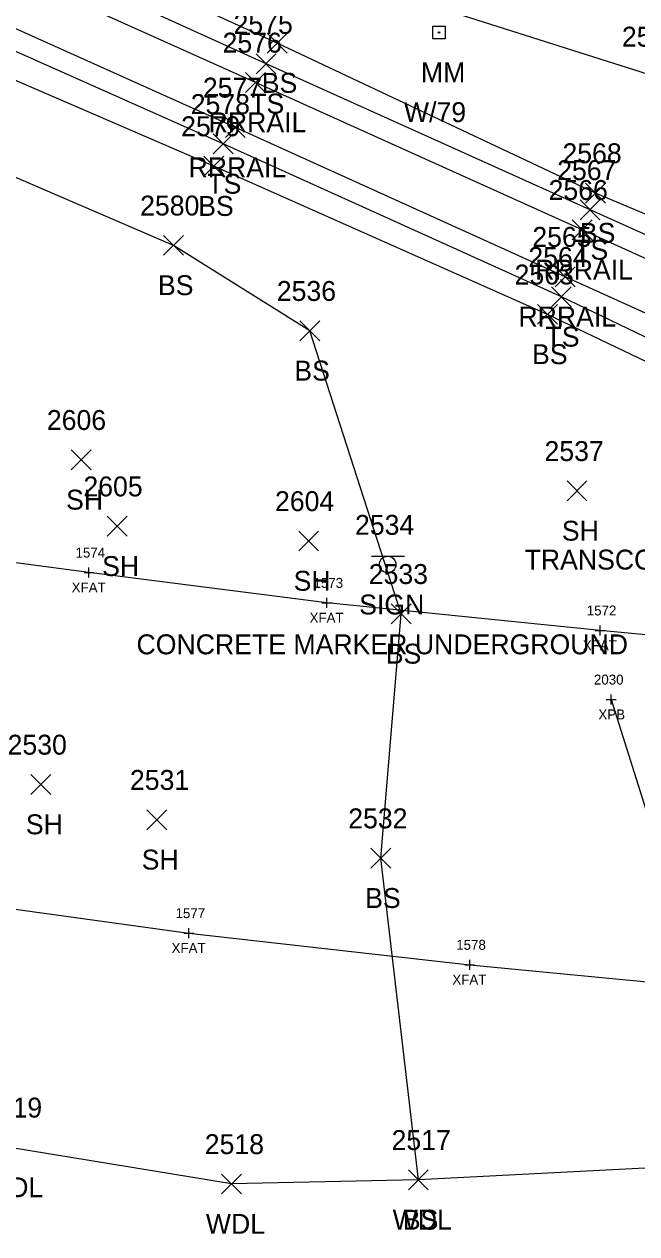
# Model space of a CAD drawing. Extents: x 1599569 to 1610055, y 642560 to 647860.
# Drawn here: x 1601133.3 to 1601194.8, y 647218.8 to 647340.3 of the extents above; entities that cross this region are included whole.
import ezdxf

# ---------------------------------------------------------------- set-up
doc = ezdxf.new("R2010")
doc.units = 0
for name, color, linetype in [('B_A', 7, 'Continuous'), ('B_I', 7, 'Continuous'), ('B_TIC', 7, 'Continuous'), ('BF', 7, 'Continuous'), ('BSUBM', 7, 'Continuous'), ('L_A', 7, 'Continuous'), ('L_I', 7, 'Continuous'), ('L_TIC', 7, 'Continuous'), ('LAWA', 7, 'Continuous'), ('LELB', 7, 'Continuous'), ('R_A', 7, 'Continuous'), ('R_I', 7, 'Continuous'), ('R_TIC', 7, 'Continuous'), ('RR', 7, 'Continuous'), ('S_A', 7, 'Continuous'), ('S_C', 7, 'Continuous'), ('S_I', 7, 'Continuous'), ('SRM', 7, 'Continuous'), ('SSGN', 7, 'Continuous')]:
    doc.layers.add(name, color=color, linetype=linetype)

msp = doc.modelspace()

# ---------------------------------------------------------------- linework, layer by layer
at = {"layer": 'B_TIC'}
for p, q in [((1601139.85, 647285.25), (1601139.93, 647285.25)), ((1601163.73, 647282.21), (1601163.81, 647282.21)), ((1601191.16, 647279.44), (1601191.24, 647279.44)), ((1601192.25, 647272.5), (1601192.33, 647272.5)), ((1601149.89, 647249.04), (1601149.96, 647249.04)), ((1601178.06, 647245.86), (1601178.14, 647245.86))]:
    msp.add_line(p, q, dxfattribs=at)
for points in [[(1601139.85, 647284.75), (1601139.85, 647285.75)], [(1601139.35, 647285.25), (1601140.35, 647285.25)], [(1601163.23, 647282.21), (1601164.23, 647282.21)], [(1601163.73, 647281.71), (1601163.73, 647282.71)], [(1601191.16, 647278.94), (1601191.16, 647279.94)], [(1601190.66, 647279.44), (1601191.66, 647279.44)], [(1601191.75, 647272.5), (1601192.75, 647272.5)], [(1601192.25, 647272), (1601192.25, 647273)], [(1601149.88, 647248.54), (1601149.88, 647249.54)], [(1601149.38, 647249.04), (1601150.38, 647249.04)], [(1601177.56, 647245.86), (1601178.56, 647245.86)], [(1601178.06, 647245.36), (1601178.06, 647246.36)]]:
    msp.add_lwpolyline(points, dxfattribs=at)
at = {"layer": 'BF'}
for points in [[(1601321.94, 647272.73), (1601290.34, 647273.17), (1601259.98, 647274.32), (1601229.43, 647276.17), (1601206.22, 647277.99), (1601191.16, 647279.44), (1601163.73, 647282.21), (1601139.85, 647285.25), (1601124.64, 647287.26)], [(1601119.61, 647253.21), (1601149.88, 647249.04), (1601178.06, 647245.86), (1601200.07, 647243.74), (1601226.76, 647241.55), (1601258.61, 647239.74), (1601288.62, 647238.61), (1601320.66, 647238.01)]]:
    msp.add_lwpolyline(points, dxfattribs=at)
at = {"layer": 'BSUBM'}
msp.add_lwpolyline([(1601192.25, 647272.5), (1601199.21, 647250.42)], dxfattribs=at)
at = {"layer": 'L_TIC'}
for points in [[(1601157.75, 647337.43), (1601159.75, 647339.43)], [(1601159.75, 647337.43), (1601157.75, 647339.43)], [(1601156.62, 647335.35), (1601158.62, 647337.35)], [(1601158.62, 647335.35), (1601156.62, 647337.35)], [(1601152.32, 647327.3), (1601154.32, 647329.3)], [(1601154.32, 647327.3), (1601152.32, 647329.3)], [(1601151.37, 647325.07), (1601153.37, 647327.07)], [(1601153.37, 647325.07), (1601151.37, 647327.07)], [(1601189.68, 647322.36), (1601191.68, 647324.36)], [(1601191.68, 647322.36), (1601189.68, 647324.36)], [(1601189.14, 647320.67), (1601191.14, 647322.67)], [(1601191.14, 647320.67), (1601189.14, 647322.67)], [(1601147.33, 647317.11), (1601149.33, 647319.11)], [(1601149.33, 647317.11), (1601147.33, 647319.11)], [(1601186.26, 647311.94), (1601188.26, 647313.94)], [(1601188.26, 647311.94), (1601186.26, 647313.94)], [(1601184.88, 647310.18), (1601186.88, 647312.18)], [(1601186.88, 647310.18), (1601184.88, 647312.18)], [(1601161.02, 647308.53), (1601163.02, 647310.53)], [(1601163.02, 647308.53), (1601161.02, 647310.53)], [(1601138.06, 647295.57), (1601140.06, 647297.57)], [(1601140.06, 647295.57), (1601138.06, 647297.57)], [(1601187.83, 647292.45), (1601189.83, 647294.45)], [(1601189.83, 647292.45), (1601187.83, 647294.45)], [(1601141.68, 647288.9), (1601143.68, 647290.9)], [(1601143.68, 647288.9), (1601141.68, 647290.9)], [(1601160.9, 647287.42), (1601162.9, 647289.42)], [(1601162.9, 647287.42), (1601160.9, 647289.42)], [(1601170.19, 647280.1), (1601172.19, 647282.1)], [(1601172.19, 647280.1), (1601170.19, 647282.1)], [(1601134.03, 647262.96), (1601136.03, 647264.96)], [(1601136.03, 647262.96), (1601134.03, 647264.96)], [(1601145.65, 647259.42), (1601147.65, 647261.42)], [(1601147.65, 647259.42), (1601145.65, 647261.42)], [(1601168.13, 647255.56), (1601170.13, 647257.56)], [(1601170.13, 647255.56), (1601168.13, 647257.56)], [(1601171.91, 647223.25), (1601173.91, 647225.25)], [(1601173.91, 647223.25), (1601171.91, 647225.25)], [(1601171.91, 647223.25), (1601173.91, 647225.25)], [(1601173.91, 647223.25), (1601171.91, 647225.25)], [(1601153.16, 647222.84), (1601155.16, 647224.84)], [(1601155.16, 647222.84), (1601153.16, 647224.84)]]:
    msp.add_lwpolyline(points, dxfattribs=at)
at = {"layer": 'LAWA'}
msp.add_lwpolyline([(1601306.6, 647220.69), (1601276.84, 647227.54), (1601234.69, 647231.8), (1601218.85, 647229.04), (1601213.51, 647228.99), (1601209.45, 647227.68), (1601199.57, 647225.62), (1601172.91, 647224.25), (1601154.16, 647223.84), (1601131.9, 647227.51), (1601118.99, 647241.56), (1601106.98, 647246.07), (1601045.88, 647251.39), (1601009.79, 647259.81), (1600973.15, 647266.08), (1600946.11, 647265.67), (1600904.1, 647280.51), (1600862.74, 647296.26), (1600826.18, 647313.68), (1600771.19, 647334.59)], dxfattribs=at)
at = {"layer": 'LELB'}
for points in [[(1601329.86, 647260.18), (1601292.61, 647278.06), (1601262.72, 647292.4), (1601226.59, 647308.21), (1601190.68, 647323.36), (1601158.75, 647338.43), (1601129.91, 647351.62), (1601096.68, 647366.43), (1601056.58, 647384.54), (1601012.74, 647404.18), (1600965.22, 647426.07), (1600914.49, 647448.77), (1600866.79, 647471.13), (1600821.34, 647492.23), (1600763.72, 647518.52)], [(1601329.08, 647258.95), (1601292.39, 647275.61), (1601261.46, 647289.71), (1601225.27, 647305.87), (1601190.14, 647321.67), (1601157.62, 647336.35), (1601128.98, 647349.36), (1601095.53, 647364.39), (1601055.96, 647382.57), (1601011.7, 647402.22), (1600964.35, 647423.93), (1600913.28, 647446.74), (1600865.78, 647468.67), (1600819.14, 647488.99), (1600762.95, 647515.26)], [(1601326.17, 647250.65), (1601291.06, 647266.1), (1601257.88, 647281.25), (1601220.45, 647296.99), (1601187.26, 647312.94), (1601153.32, 647328.3), (1601124.87, 647340.95), (1601091.41, 647355.79), (1601053.43, 647373.03), (1601007.18, 647393.84), (1600960.43, 647415.03), (1600909.23, 647438.57), (1600861.95, 647459.92), (1600814.78, 647480.92), (1600758.97, 647506.06)], [(1601324.87, 647247.72), (1601290.33, 647262.4), (1601257.07, 647278.05), (1601219.4, 647295.14), (1601185.88, 647311.18), (1601152.37, 647326.07), (1601123.71, 647338.45), (1601090.36, 647353.63), (1601052.5, 647371.13), (1601006, 647391.96), (1600959.19, 647412.11), (1600907.65, 647435.58), (1600860.78, 647455.97), (1600813.3, 647477.78), (1600757.71, 647501.96)], [(1601277.64, 647306.94), (1601247.91, 647313.96), (1601233.47, 647321.04), (1601196.65, 647335.07), (1601162.36, 647345.97), (1601131.17, 647354.49), (1601097.9, 647368.75), (1601057.17, 647386.63), (1601013.7, 647406.22), (1600966.1, 647427.78), (1600916.08, 647451.44), (1600867.43, 647472.68), (1600824.54, 647496.94)], [(1601172.91, 647224.25), (1601169.13, 647256.56), (1601171.19, 647281.1), (1601162.02, 647309.53), (1601148.33, 647318.11), (1601119.88, 647330.36), (1601083.79, 647337.85), (1601042.57, 647341.43), (1601006.37, 647351.71), (1600962.47, 647358.64), (1600928.59, 647369.58)]]:
    msp.add_lwpolyline(points, dxfattribs=at)
at = {"layer": 'R_TIC'}
for points in [[(1601155.57, 647333.47), (1601157.57, 647335.47)], [(1601157.57, 647333.47), (1601155.57, 647335.47)], [(1601153.54, 647328.95), (1601155.54, 647330.95)], [(1601155.54, 647328.95), (1601153.54, 647330.95)], [(1601188.34, 647318.67), (1601190.34, 647320.67)], [(1601190.34, 647318.67), (1601188.34, 647320.67)], [(1601186.65, 647313.96), (1601188.65, 647315.96)], [(1601188.65, 647313.96), (1601186.65, 647315.96)]]:
    msp.add_lwpolyline(points, dxfattribs=at)
at = {"layer": 'RR'}
for points in [[(1601328.26, 647256.93), (1601292.48, 647273.14), (1601260.65, 647287.58), (1601223.96, 647303.96), (1601189.34, 647319.67), (1601156.57, 647334.47), (1601128.05, 647347.29), (1601094.57, 647362.49), (1601054.86, 647380.37), (1601010.55, 647400.2), (1600963.24, 647421.51), (1600912.09, 647444.53), (1600864.46, 647466.02), (1600817.98, 647486.96), (1600761.67, 647512.45)], [(1601326.5, 647252.29), (1601291.28, 647268.22), (1601258.56, 647283.04), (1601221.6, 647299.6), (1601187.65, 647314.96), (1601154.54, 647329.95), (1601125.78, 647342.91), (1601092.45, 647357.88), (1601054.06, 647375.24), (1601008.5, 647395.78), (1600961.24, 647417), (1600909.88, 647440.14), (1600862.44, 647461.47), (1600815.63, 647482.59), (1600759.94, 647507.87)]]:
    msp.add_lwpolyline(points, dxfattribs=at)
at = {"layer": 'SRM'}
msp.add_lwpolyline([(1601174.36, 647340.12), (1601175.61, 647340.12), (1601175.61, 647338.87), (1601174.36, 647338.87)], close=True, dxfattribs=at)
msp.add_circle((1601174.98, 647339.49), 0.0833, dxfattribs=at)
at = {"layer": 'SSGN'}
for p, q in [((1601168.19, 647286.89), (1601171.52, 647286.89)), ((1601169.83, 647286.06), (1601169.83, 647286.06))]:
    msp.add_line(p, q, dxfattribs=at)
msp.add_circle((1601169.83, 647286.06), 0.833, dxfattribs=at)

# ---------------------------------------------------------------- texts
at = {"layer": 'B_A'}
for s, p in [('XFAT', (1601138.11, 647283.25)), ('XFAT', (1601161.99, 647280.21)), ('XFAT', (1601189.42, 647277.44)), ('XPB', (1601190.98, 647270.5)), ('XFAT', (1601148.14, 647247.04)), ('XFAT', (1601176.32, 647243.86))]:
    msp.add_text(s, height=1, dxfattribs=at).set_placement(p)
at = {"layer": 'B_I'}
for s, p in [('1574', (1601138.5, 647286.75)), ('1573', (1601162.38, 647283.71)), ('1572', (1601189.81, 647280.94)), ('2030', (1601190.53, 647274)), ('1577', (1601148.54, 647250.54)), ('1578', (1601176.71, 647247.36))]:
    msp.add_text(s, height=1, dxfattribs=at).set_placement(p)
at = {"layer": 'L_A'}
for s, p in [('BS', (1601157.19, 647333.43)), ('TS', (1601156.03, 647331.35)), ('TS', (1601151.73, 647323.3)), ('BS', (1601150.81, 647321.07)), ('BS', (1601189.12, 647318.36)), ('TS', (1601188.55, 647316.67)), ('BS', (1601146.77, 647313.11)), ('TS', (1601185.67, 647307.94)), ('BS', (1601184.32, 647306.18)), ('BS', (1601160.46, 647304.53)), ('SH', (1601137.55, 647291.57)), ('SH', (1601187.31, 647288.45)), ('SH', (1601141.17, 647284.9)), ('SH', (1601160.39, 647283.42)), ('BS', (1601169.64, 647276.1)), ('SH', (1601133.51, 647258.96)), ('SH', (1601145.14, 647255.42)), ('BS', (1601167.57, 647251.56)), ('WDL', (1601129.32, 647222.51)), ('WDL', (1601170.33, 647219.25)), ('BS', (1601171.35, 647219.25)), ('WDL', (1601151.58, 647218.84))]:
    msp.add_text(s, height=2, dxfattribs=at).set_placement(p)
at = {"layer": 'L_I'}
for s, p in [('2575', (1601154.36, 647339.35)), ('2569', (1601193.34, 647338.07)), ('2578', (1601150.06, 647331.3)), ('2579', (1601149.1, 647329.07)), ('2568', (1601187.37, 647326.36)), ('2567', (1601186.84, 647324.67)), ('2580', (1601144.98, 647321.11)), ('2564', (1601183.95, 647315.94)), ('2563', (1601182.57, 647314.18)), ('2536', (1601158.7, 647312.53)), ('2606', (1601135.62, 647299.57)), ('2537', (1601185.57, 647296.45)), ('2605', (1601139.29, 647292.9)), ('2604', (1601158.52, 647291.42)), ('2533', (1601167.93, 647284.1)), ('2530', (1601131.68, 647266.96)), ('2531', (1601143.96, 647263.42)), ('2532', (1601165.87, 647259.56)), ('2519', (1601129.2, 647230.51)), ('2518', (1601151.47, 647226.84)), ('2517', (1601170.22, 647227.25)), ('2517', (1601170.22, 647227.25))]:
    msp.add_text(s, height=2, dxfattribs=at).set_placement(p)
at = {"layer": 'R_A'}
for p in [(1601151.86, 647329.47), (1601149.84, 647324.95), (1601184.64, 647314.67), (1601182.95, 647309.96)]:
    msp.add_text('RRRAIL', height=2, dxfattribs=at).set_placement(p)
at = {"layer": 'R_I'}
for s, p in [('2576', (1601153.26, 647337.47)), ('2577', (1601151.28, 647332.95)), ('2566', (1601185.98, 647322.67)), ('2565', (1601184.35, 647317.96))]:
    msp.add_text(s, height=2, dxfattribs=at).set_placement(p)
at = {"layer": 'S_A'}
for s, p in [('MM', (1601173.17, 647334.49)), ('SIGN', (1601166.97, 647281.04))]:
    msp.add_text(s, height=2, dxfattribs=at).set_placement(p)
at = {"layer": 'S_C'}
for s, p in [('W/79', (1601171.46, 647330.49)), ('TRANSCONTINENTAL CABLE', (1601183.57, 647285.55)), ('CONCRETE MARKER UNDERGROUND', (1601144.62, 647277.04))]:
    msp.add_text(s, height=2, dxfattribs=at).set_placement(p)
at = {"layer": 'S_I'}
msp.add_text('2534', height=2, dxfattribs=at).set_placement((1601166.55, 647289.04))

doc.saveas('drawing.dxf')
